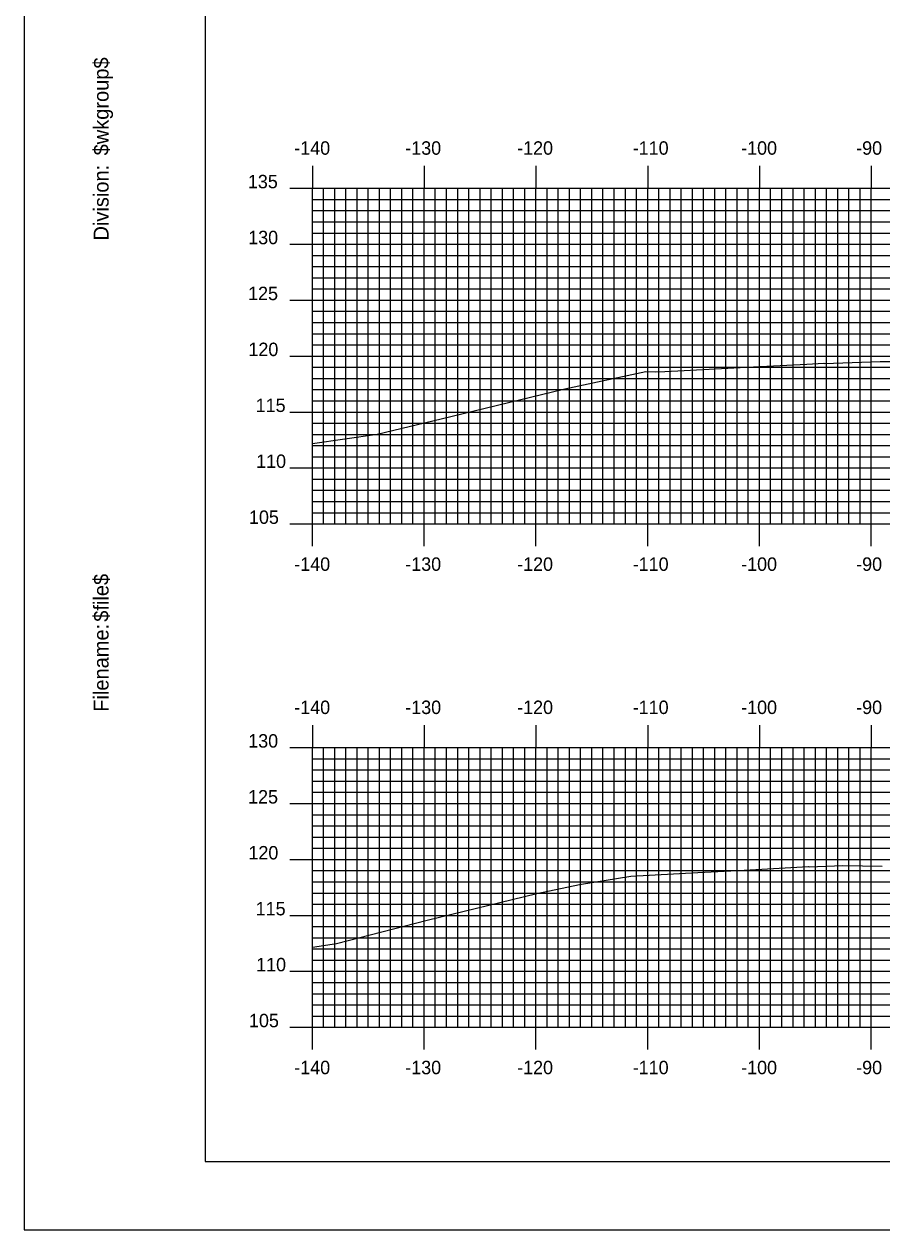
# Model space of a CAD drawing. Extents: x 1686373 to 1686716, y 461260 to 461480.
# Drawn here: x 1686373 to 1686449.7, y 461260 to 461367.7 of the extents above; entities that cross this region are included whole.
import ezdxf

# ---------------------------------------------------------------- set-up
doc = ezdxf.new("R2010")
doc.units = 0
for name, color, linetype in [('BORDER', 7, 'Continuous'), ('H_V ANNOTATION', 7, 'Continuous'), ('M_Roadway_Centerline', 7, 'Continuous'), ('MAJOR', 7, 'Continuous'), ('MINOR', 7, 'Continuous'), ('PLOT BOUNDARY', 7, 'Continuous'), ('S_Roadway_Centerline', 7, 'Continuous')]:
    doc.layers.add(name, color=color, linetype=linetype)

msp = doc.modelspace()

# ---------------------------------------------------------------- linework, layer by layer
at = {"layer": 'BORDER'}
msp.add_lwpolyline([(1686389.17, 461266.07), (1686709.17, 461266.07), (1686709.17, 461476.07), (1686389.17, 461476.07)], close=True, dxfattribs=at)
at = {"layer": 'MAJOR'}
for p, q in [((1686398.77, 461355.08), (1686398.77, 461353.07)), ((1686408.77, 461355.08), (1686408.77, 461353.07)), ((1686418.77, 461355.08), (1686418.77, 461353.07)), ((1686428.77, 461355.08), (1686428.77, 461353.07)), ((1686438.77, 461355.08), (1686438.77, 461353.07)), ((1686448.77, 461355.08), (1686448.77, 461353.07)), ((1686396.76, 461353.07), (1686398.77, 461353.07)), ((1686398.77, 461353.07), (1686678.77, 461353.07)), ((1686398.77, 461323.07), (1686398.77, 461353.07)), ((1686398.77, 461323.07), (1686398.77, 461353.07)), ((1686398.77, 461353.07), (1686678.77, 461353.07)), ((1686408.77, 461323.07), (1686408.77, 461353.07)), ((1686418.77, 461323.07), (1686418.77, 461353.07)), ((1686428.77, 461323.07), (1686428.77, 461353.07)), ((1686438.77, 461323.07), (1686438.77, 461353.07)), ((1686448.77, 461323.07), (1686448.77, 461353.07)), ((1686396.76, 461348.07), (1686398.77, 461348.07)), ((1686398.77, 461348.07), (1686678.77, 461348.07)), ((1686396.76, 461343.07), (1686398.77, 461343.07)), ((1686398.77, 461343.07), (1686678.77, 461343.07)), ((1686396.76, 461338.07), (1686398.77, 461338.07)), ((1686398.77, 461338.07), (1686678.77, 461338.07)), ((1686396.76, 461333.07), (1686398.77, 461333.07)), ((1686398.77, 461333.07), (1686678.77, 461333.07)), ((1686396.76, 461328.07), (1686398.77, 461328.07)), ((1686398.77, 461328.07), (1686678.77, 461328.07)), ((1686396.76, 461323.07), (1686398.77, 461323.07)), ((1686398.77, 461323.07), (1686678.77, 461323.07)), ((1686398.77, 461323.07), (1686678.77, 461323.07)), ((1686398.77, 461321.07), (1686398.77, 461323.07)), ((1686408.77, 461321.07), (1686408.77, 461323.07)), ((1686418.77, 461321.07), (1686418.77, 461323.07)), ((1686428.77, 461321.07), (1686428.77, 461323.07)), ((1686438.77, 461321.07), (1686438.77, 461323.07)), ((1686448.77, 461321.07), (1686448.77, 461323.07)), ((1686398.77, 461305.08), (1686398.77, 461303.07)), ((1686408.77, 461305.08), (1686408.77, 461303.07)), ((1686418.77, 461305.08), (1686418.77, 461303.07)), ((1686428.77, 461305.08), (1686428.77, 461303.07)), ((1686438.77, 461305.08), (1686438.77, 461303.07)), ((1686448.77, 461305.08), (1686448.77, 461303.07)), ((1686396.76, 461303.07), (1686398.77, 461303.07)), ((1686398.77, 461303.07), (1686678.77, 461303.07)), ((1686398.77, 461278.07), (1686398.77, 461303.07)), ((1686398.77, 461278.07), (1686398.77, 461303.07)), ((1686398.77, 461303.07), (1686678.77, 461303.07)), ((1686408.77, 461278.07), (1686408.77, 461303.07)), ((1686418.77, 461278.07), (1686418.77, 461303.07)), ((1686428.77, 461278.07), (1686428.77, 461303.07)), ((1686438.77, 461278.07), (1686438.77, 461303.07)), ((1686448.77, 461278.07), (1686448.77, 461303.07)), ((1686396.76, 461298.07), (1686398.77, 461298.07)), ((1686398.77, 461298.07), (1686678.77, 461298.07)), ((1686396.76, 461293.07), (1686398.77, 461293.07)), ((1686398.77, 461293.07), (1686678.77, 461293.07)), ((1686396.76, 461288.07), (1686398.77, 461288.07)), ((1686398.77, 461288.07), (1686678.77, 461288.07)), ((1686396.76, 461283.07), (1686398.77, 461283.07)), ((1686398.77, 461283.07), (1686678.77, 461283.07)), ((1686396.76, 461278.07), (1686398.77, 461278.07)), ((1686398.77, 461278.07), (1686678.77, 461278.07)), ((1686398.77, 461278.07), (1686678.77, 461278.07)), ((1686398.77, 461276.07), (1686398.77, 461278.07)), ((1686408.77, 461276.07), (1686408.77, 461278.07)), ((1686418.77, 461276.07), (1686418.77, 461278.07)), ((1686428.77, 461276.07), (1686428.77, 461278.07)), ((1686438.77, 461276.07), (1686438.77, 461278.07)), ((1686448.77, 461276.07), (1686448.77, 461278.07))]:
    msp.add_line(p, q, dxfattribs=at)
at = {"layer": 'MINOR'}
for p, q in [((1686398.77, 461352.07), (1686678.77, 461352.07)), ((1686398.77, 461352.07), (1686400.77, 461352.07)), ((1686399.77, 461323.07), (1686399.77, 461353.07)), ((1686400.77, 461323.07), (1686400.77, 461353.07)), ((1686401.77, 461323.07), (1686401.77, 461353.07)), ((1686402.77, 461323.07), (1686402.77, 461353.07)), ((1686403.77, 461323.07), (1686403.77, 461353.07)), ((1686404.77, 461323.07), (1686404.77, 461353.07)), ((1686405.77, 461323.07), (1686405.77, 461353.07)), ((1686406.77, 461323.07), (1686406.77, 461353.07)), ((1686407.77, 461323.07), (1686407.77, 461353.07)), ((1686409.77, 461323.07), (1686409.77, 461353.07)), ((1686410.77, 461323.07), (1686410.77, 461353.07)), ((1686411.77, 461323.07), (1686411.77, 461353.07)), ((1686412.77, 461323.07), (1686412.77, 461353.07)), ((1686413.77, 461323.07), (1686413.77, 461353.07)), ((1686414.77, 461323.07), (1686414.77, 461353.07)), ((1686415.77, 461323.07), (1686415.77, 461353.07)), ((1686416.77, 461323.07), (1686416.77, 461353.07)), ((1686417.77, 461323.07), (1686417.77, 461353.07)), ((1686419.77, 461323.07), (1686419.77, 461353.07)), ((1686420.77, 461323.07), (1686420.77, 461353.07)), ((1686421.77, 461323.07), (1686421.77, 461353.07)), ((1686422.77, 461323.07), (1686422.77, 461353.07)), ((1686423.77, 461323.07), (1686423.77, 461353.07)), ((1686424.77, 461323.07), (1686424.77, 461353.07)), ((1686425.77, 461323.07), (1686425.77, 461353.07)), ((1686426.77, 461323.07), (1686426.77, 461353.07)), ((1686427.77, 461323.07), (1686427.77, 461353.07)), ((1686429.77, 461323.07), (1686429.77, 461353.07)), ((1686430.77, 461323.07), (1686430.77, 461353.07)), ((1686431.77, 461323.07), (1686431.77, 461353.07)), ((1686432.77, 461323.07), (1686432.77, 461353.07)), ((1686433.77, 461323.07), (1686433.77, 461353.07)), ((1686434.77, 461323.07), (1686434.77, 461353.07)), ((1686435.77, 461323.07), (1686435.77, 461353.07)), ((1686436.77, 461323.07), (1686436.77, 461353.07)), ((1686437.77, 461323.07), (1686437.77, 461353.07)), ((1686439.77, 461323.07), (1686439.77, 461353.07)), ((1686440.77, 461323.07), (1686440.77, 461353.07)), ((1686441.77, 461323.07), (1686441.77, 461353.07)), ((1686442.77, 461323.07), (1686442.77, 461353.07)), ((1686443.77, 461323.07), (1686443.77, 461353.07)), ((1686444.77, 461323.07), (1686444.77, 461353.07)), ((1686445.77, 461323.07), (1686445.77, 461353.07)), ((1686446.77, 461323.07), (1686446.77, 461353.07)), ((1686447.77, 461323.07), (1686447.77, 461353.07)), ((1686398.77, 461351.07), (1686678.77, 461351.07)), ((1686398.77, 461351.07), (1686400.77, 461351.07)), ((1686398.77, 461350.07), (1686678.77, 461350.07)), ((1686398.77, 461350.07), (1686400.77, 461350.07)), ((1686398.77, 461349.07), (1686678.77, 461349.07)), ((1686398.77, 461349.07), (1686400.77, 461349.07)), ((1686398.77, 461347.07), (1686678.77, 461347.07)), ((1686398.77, 461347.07), (1686400.77, 461347.07)), ((1686398.77, 461346.07), (1686678.77, 461346.07)), ((1686398.77, 461346.07), (1686400.77, 461346.07)), ((1686398.77, 461345.07), (1686678.77, 461345.07)), ((1686398.77, 461345.07), (1686400.77, 461345.07)), ((1686398.77, 461344.07), (1686678.77, 461344.07)), ((1686398.77, 461344.07), (1686400.77, 461344.07)), ((1686398.77, 461342.07), (1686678.77, 461342.07)), ((1686398.77, 461342.07), (1686400.77, 461342.07)), ((1686398.77, 461341.07), (1686678.77, 461341.07)), ((1686398.77, 461341.07), (1686400.77, 461341.07)), ((1686398.77, 461340.07), (1686678.77, 461340.07)), ((1686398.77, 461340.07), (1686400.77, 461340.07)), ((1686398.77, 461339.07), (1686678.77, 461339.07)), ((1686398.77, 461339.07), (1686400.77, 461339.07)), ((1686398.77, 461337.07), (1686678.77, 461337.07)), ((1686398.77, 461337.07), (1686400.77, 461337.07)), ((1686398.77, 461336.07), (1686678.77, 461336.07)), ((1686398.77, 461336.07), (1686400.77, 461336.07)), ((1686398.77, 461335.07), (1686678.77, 461335.07)), ((1686398.77, 461335.07), (1686400.77, 461335.07)), ((1686398.77, 461334.07), (1686678.77, 461334.07)), ((1686398.77, 461334.07), (1686400.77, 461334.07)), ((1686398.77, 461332.07), (1686678.77, 461332.07)), ((1686398.77, 461332.07), (1686400.77, 461332.07)), ((1686398.77, 461331.07), (1686678.77, 461331.07)), ((1686398.77, 461331.07), (1686400.77, 461331.07)), ((1686398.77, 461330.07), (1686678.77, 461330.07)), ((1686398.77, 461330.07), (1686400.77, 461330.07)), ((1686398.77, 461329.07), (1686678.77, 461329.07)), ((1686398.77, 461329.07), (1686400.77, 461329.07)), ((1686398.77, 461327.07), (1686678.77, 461327.07)), ((1686398.77, 461327.07), (1686400.77, 461327.07)), ((1686398.77, 461326.07), (1686678.77, 461326.07)), ((1686398.77, 461326.07), (1686400.77, 461326.07)), ((1686398.77, 461325.07), (1686678.77, 461325.07)), ((1686398.77, 461325.07), (1686400.77, 461325.07)), ((1686398.77, 461324.07), (1686678.77, 461324.07)), ((1686398.77, 461324.07), (1686400.77, 461324.07)), ((1686399.77, 461278.07), (1686399.77, 461303.07)), ((1686400.77, 461278.07), (1686400.77, 461303.07)), ((1686401.77, 461278.07), (1686401.77, 461303.07)), ((1686402.77, 461278.07), (1686402.77, 461303.07)), ((1686403.77, 461278.07), (1686403.77, 461303.07)), ((1686404.77, 461278.07), (1686404.77, 461303.07)), ((1686405.77, 461278.07), (1686405.77, 461303.07)), ((1686406.77, 461278.07), (1686406.77, 461303.07)), ((1686407.77, 461278.07), (1686407.77, 461303.07)), ((1686409.77, 461278.07), (1686409.77, 461303.07)), ((1686410.77, 461278.07), (1686410.77, 461303.07)), ((1686411.77, 461278.07), (1686411.77, 461303.07)), ((1686412.77, 461278.07), (1686412.77, 461303.07)), ((1686413.77, 461278.07), (1686413.77, 461303.07)), ((1686414.77, 461278.07), (1686414.77, 461303.07)), ((1686415.77, 461278.07), (1686415.77, 461303.07)), ((1686416.77, 461278.07), (1686416.77, 461303.07)), ((1686417.77, 461278.07), (1686417.77, 461303.07)), ((1686419.77, 461278.07), (1686419.77, 461303.07)), ((1686420.77, 461278.07), (1686420.77, 461303.07)), ((1686421.77, 461278.07), (1686421.77, 461303.07)), ((1686422.77, 461278.07), (1686422.77, 461303.07)), ((1686423.77, 461278.07), (1686423.77, 461303.07)), ((1686424.77, 461278.07), (1686424.77, 461303.07)), ((1686425.77, 461278.07), (1686425.77, 461303.07)), ((1686426.77, 461278.07), (1686426.77, 461303.07)), ((1686427.77, 461278.07), (1686427.77, 461303.07)), ((1686429.77, 461278.07), (1686429.77, 461303.07)), ((1686430.77, 461278.07), (1686430.77, 461303.07)), ((1686431.77, 461278.07), (1686431.77, 461303.07)), ((1686432.77, 461278.07), (1686432.77, 461303.07)), ((1686433.77, 461278.07), (1686433.77, 461303.07)), ((1686434.77, 461278.07), (1686434.77, 461303.07)), ((1686435.77, 461278.07), (1686435.77, 461303.07)), ((1686436.77, 461278.07), (1686436.77, 461303.07)), ((1686437.77, 461278.07), (1686437.77, 461303.07)), ((1686439.77, 461278.07), (1686439.77, 461303.07)), ((1686440.77, 461278.07), (1686440.77, 461303.07)), ((1686441.77, 461278.07), (1686441.77, 461303.07)), ((1686442.77, 461278.07), (1686442.77, 461303.07)), ((1686443.77, 461278.07), (1686443.77, 461303.07)), ((1686444.77, 461278.07), (1686444.77, 461303.07)), ((1686445.77, 461278.07), (1686445.77, 461303.07)), ((1686446.77, 461278.07), (1686446.77, 461303.07)), ((1686447.77, 461278.07), (1686447.77, 461303.07)), ((1686398.77, 461302.07), (1686678.77, 461302.07)), ((1686398.77, 461302.07), (1686400.77, 461302.07)), ((1686398.77, 461301.07), (1686678.77, 461301.07)), ((1686398.77, 461301.07), (1686400.77, 461301.07)), ((1686398.77, 461300.07), (1686678.77, 461300.07)), ((1686398.77, 461300.07), (1686400.77, 461300.07)), ((1686398.77, 461299.07), (1686678.77, 461299.07)), ((1686398.77, 461299.07), (1686400.77, 461299.07)), ((1686398.77, 461297.07), (1686678.77, 461297.07)), ((1686398.77, 461297.07), (1686400.77, 461297.07)), ((1686398.77, 461296.07), (1686678.77, 461296.07)), ((1686398.77, 461296.07), (1686400.77, 461296.07)), ((1686398.77, 461295.07), (1686678.77, 461295.07)), ((1686398.77, 461295.07), (1686400.77, 461295.07)), ((1686398.77, 461294.07), (1686678.77, 461294.07)), ((1686398.77, 461294.07), (1686400.77, 461294.07)), ((1686398.77, 461292.07), (1686678.77, 461292.07)), ((1686398.77, 461292.07), (1686400.77, 461292.07)), ((1686398.77, 461291.07), (1686678.77, 461291.07)), ((1686398.77, 461291.07), (1686400.77, 461291.07)), ((1686398.77, 461290.07), (1686678.77, 461290.07)), ((1686398.77, 461290.07), (1686400.77, 461290.07)), ((1686398.77, 461289.07), (1686678.77, 461289.07)), ((1686398.77, 461289.07), (1686400.77, 461289.07)), ((1686398.77, 461287.07), (1686678.77, 461287.07)), ((1686398.77, 461287.07), (1686400.77, 461287.07)), ((1686398.77, 461286.07), (1686678.77, 461286.07)), ((1686398.77, 461286.07), (1686400.77, 461286.07)), ((1686398.77, 461285.07), (1686678.77, 461285.07)), ((1686398.77, 461285.07), (1686400.77, 461285.07)), ((1686398.77, 461284.07), (1686678.77, 461284.07)), ((1686398.77, 461284.07), (1686400.77, 461284.07)), ((1686398.77, 461282.07), (1686678.77, 461282.07)), ((1686398.77, 461282.07), (1686400.77, 461282.07)), ((1686398.77, 461281.07), (1686678.77, 461281.07)), ((1686398.77, 461281.07), (1686400.77, 461281.07)), ((1686398.77, 461280.07), (1686678.77, 461280.07)), ((1686398.77, 461280.07), (1686400.77, 461280.07)), ((1686398.77, 461279.07), (1686678.77, 461279.07)), ((1686398.77, 461279.07), (1686400.77, 461279.07))]:
    msp.add_line(p, q, dxfattribs=at)
at = {"layer": 'PLOT BOUNDARY'}
msp.add_lwpolyline([(1686372.98, 461259.95), (1686712.98, 461259.95), (1686712.98, 461479.95), (1686372.98, 461479.95)], close=True, dxfattribs=at)
at = {"layer": 'S_Roadway_Centerline'}
for points in [[(1686398.77, 461330.24), (1686404.58, 461331.08), (1686410.3, 461332.46), (1686421.37, 461335.14), (1686428.59, 461336.69), (1686429.51, 461336.65), (1686430.3, 461336.69), (1686432.04, 461336.77), (1686437.04, 461337.06), (1686443.02, 461337.34), (1686444.54, 461337.43), (1686444.56, 461337.41), (1686449.57, 461337.57), (1686454.38, 461337.57)], [(1686398.77, 461285.24), (1686400.92, 461285.55), (1686409.05, 461287.65), (1686418.86, 461290.02), (1686422.66, 461290.84), (1686427.27, 461291.58), (1686433.26, 461291.9), (1686437.41, 461292.1), (1686443.16, 461292.44), (1686443.21, 461292.4), (1686446.23, 461292.52), (1686449.76, 461292.48)]]:
    msp.add_lwpolyline(points, dxfattribs=at)

# ---------------------------------------------------------------- texts
at = {"layer": 'BORDER'}
for s, p in [('$wkgroup$', (1686380.54, 461356.01)), ('Division:', (1686380.54, 461348.4)), ('$file$', (1686380.54, 461314.32)), ('Filename:', (1686380.54, 461306.27))]:
    msp.add_text(s, height=1.339, rotation=90, dxfattribs=at).set_placement(p)
at = {"layer": 'H_V ANNOTATION'}
for s, p in [('-140', (1686397.15, 461356.07)), ('-130', (1686407.08, 461356.07)), ('-120', (1686417.09, 461356.07)), ('-110', (1686427.43, 461356.07)), ('-100', (1686437.13, 461356.07)), ('-90', (1686447.42, 461356.07)), ('135', (1686393, 461353.07)), ('130', (1686393.03, 461348.07)), ('125', (1686393.02, 461343.07)), ('120', (1686393.05, 461338.07)), ('115', (1686393.7, 461333.07)), ('110', (1686393.74, 461328.07)), ('105', (1686393.1, 461323.07)), ('-140', (1686397.15, 461318.87)), ('-130', (1686407.08, 461318.87)), ('-120', (1686417.09, 461318.87)), ('-110', (1686427.43, 461318.87)), ('-100', (1686437.13, 461318.87)), ('-90', (1686447.42, 461318.87)), ('-140', (1686397.15, 461306.07)), ('-130', (1686407.08, 461306.07)), ('-120', (1686417.09, 461306.07)), ('-110', (1686427.43, 461306.07)), ('-100', (1686437.13, 461306.07)), ('-90', (1686447.42, 461306.07)), ('130', (1686393.03, 461303.07)), ('125', (1686393.02, 461298.07)), ('120', (1686393.05, 461293.07)), ('115', (1686393.7, 461288.07)), ('110', (1686393.74, 461283.07)), ('105', (1686393.1, 461278.07)), ('-140', (1686397.15, 461273.87)), ('-130', (1686407.08, 461273.87)), ('-120', (1686417.09, 461273.87)), ('-110', (1686427.43, 461273.87)), ('-100', (1686437.13, 461273.87)), ('-90', (1686447.42, 461273.87))]:
    msp.add_text(s, height=1.2, dxfattribs=at).set_placement(p)
at = {"layer": 'M_Roadway_Centerline'}
for s, p in [('C', (1686444.53, 461337.43)), ('L', (1686444.54, 461337.43)), ('C', (1686443.16, 461292.44)), ('L', (1686443.16, 461292.44))]:
    msp.add_text(s, height=0.0146, dxfattribs=at).set_placement(p)
at = {"layer": 'MAJOR'}
for p in [(1686398.76, 461323.07), (1686398.76, 461278.07)]:
    msp.add_text('-', height=0.012, dxfattribs=at).set_placement(p)

doc.saveas('drawing.dxf')
